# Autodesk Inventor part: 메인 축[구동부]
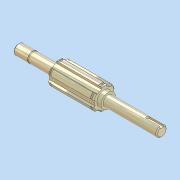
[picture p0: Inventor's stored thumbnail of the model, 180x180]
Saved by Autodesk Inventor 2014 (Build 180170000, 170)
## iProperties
Company: 한국ATC센터
Created: 2012-05
Part Number: 메인 축[구동부]
Document SubType Name: 모델링
Designer: KYOUNG IL JANG
Mass: 168.567 g
Surface Area: 72.5109 cm^2
Volume: 21.4462 cm^3
Density: 7.86 g/cm^3
Material: 강, 연강
Appearance: 강철
변환 표준: STEP AP214IS
파일 이름: C:\Users\SeoGD\Desktop\?쒗뿕\硫붿씤 異?.stp
전처리기: Build: 253, Release: 2010 SP1 - Date: Wed 07/29/2009
전송 단위: 밀리미터
불확실성: 0.01
Author: KYOUNG IL JANG
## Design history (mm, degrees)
sketch "스케치1"
  geometry: L1 (-69.5, 0)-(69.5, 0); L2 (69.5, 0)-(69.5, 5); L3 (69.5, 5)-(55.5, 5); L4 (55.5, 5)-(55.5, 4.8); L5 (55.5, 4.8)-(54.35, 4.8); L6 (54.35, 4.8)-(54.35, 5); L7 (54.35, 5)-(30.5, 5); L8 (30.5, 5)-(30.5, 9); L9 (30.5, 9)-(-13.5, 9); L10 (-13.5, 9)-(-13.5, 7); L11 (-13.5, 7)-(-17.5, 7); L12 (-17.5, 7)-(-17.5, 5); L13 (-17.5, 5)-(-69.5, 5); L14 (-69.5, 5)-(-69.5, 0); 2 further points
  constraints: 28 end point, 9 parallel, 4 collinear, 2 perpendicular, 1 coincident, 1 horizontal, 1 midpoint
  dimensions: "d2" = 1.15 distance between parallel lines of L6 L4; "d3" = 10 diameter of L3 L1; "d4" = 9.6 diameter of L5 L1; "d6" = 44 distance between parallel lines of L10 L8; "d7" = 4 distance between parallel lines of L12 L10; "d8" = 14 diameter of L11 L1; "d9" = 18 diameter of L9 L1; "d33" = 52 distance from line of L12.end L14; "d37" = 39 distance between parallel lines of L8 L2; "d38" = 14 distance between parallel lines of L2 L4
revolve "회전1" sketch "스케치1" stored, may be unused: angle "d10" = 90 deg
sketch "스케치2"
  geometry: L1 (2.5, 10.712)-(2.5, 8.646); L2 (-2.5, 10.712)-(-2.5, 8.646); A1 r 9 centre (0, 0) between (2.5, 8.646) and (-2.5, 8.646) reference; A2 r 11 centre (0, 0) between (2.5, 10.712) and (-2.5, 10.712); 1 further point
  constraints: 4 end point, 4 point on circle, 2 parallel, 1 centre point, 1 coincident, 1 vertical
  dimensions: "d11" = 22 diameter of A2; "d12" = 5 distance between parallel lines of L1 L2
extrude "돌출1" join sketch "스케치2" stored distance "d13" = 10; taper "d14" = 0 deg
chamfer "모따기1" distance "d15" = 1; stored, may be unused: second distance "d16" = 2, angle "d17" = 45 deg
node "작업 평면1"
node "작업 평면2"
sketch "스케치3"
  geometry: L1 (2.5, 10.712)-(2.5, 10.198); L2 (-2.5, 10.712)-(-2.5, 10.198); A1 r 11 centre (0, 0) between (2.5, 10.712) and (-2.5, 10.712) reference; A2 r 10.5 centre (0, 0) between (2.5, 10.198) and (-2.5, 10.198); 1 further point
  constraints: 4 end point, 2 point on circle, 1 centre point, 1 coincident, 1 parallel, 1 vertical
  dimensions: "d19" = 21 diameter of A2
extrude "돌출2" cut sketch "스케치3" distance "d20" = 1.35; taper "d21" = 0 deg
node "작업 평면3"
sketch "스케치4"
  geometry: L1 (-26, -5)-(-26, 5) reference; L2 (-26, 1.5)-(-12.5, 1.5); L3 (-12.5, -1.5)-(-26, -1.5); A1 r 1.5 centre (-12.5, 0) between (-12.5, -1.5) and (-12.5, 1.5); 2 further points
  constraints: 4 end point, 2 perpendicular, 2 point on circle, 2 point on line, 2 tangent, 1 centre point, 1 horizontal alignment, 1 midpoint
  dimensions: "d25" = 3 distance between parallel lines of L3 L2; "d26" = 15 dimension on A1 L1
extrude "돌출3" cut sketch "스케치4" distance "d27" = 1.8; taper "d28" = 0 deg
chamfer "모따기2" distance "d29" = 1; stored, may be unused: second distance "d30" = 2, angle "d31" = 45 deg
node "솔리드1"
node "솔리드 본체"
node "곡면 본체"
mirror "대칭1"
pattern_circular "원형 패턴1" dims "d23" = 360 deg
node "솔리드2"
other parameters: "d18" = -1.65
